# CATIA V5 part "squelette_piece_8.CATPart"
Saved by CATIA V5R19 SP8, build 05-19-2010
Part number: squelette_piece_8
Publications: "Droite.1", "Point.2", "Point.1", "Droite.2", "Droite.3", "Plan.1"
Bounding box of the stored display mesh (mm): x -56 to 58, y 63.5 to 66.858, z -240.184 to 345.816
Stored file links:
  G:\EU_thinkMotion\CFAO_2010\SIL_groupe1\SIL_groupe1\A reprendre\lalpha\lalpha\Alpha.mécanisme\squelette_piece_8.CATPart
  G:\EU_thinkMotion\CFAO_2010\SIL_groupe1\SIL_groupe1\A reprendre\lalpha\lalpha\Alpha.mécanisme\bielle7.CATPart
  G:\EU_thinkMotion\CFAO_2010\SIL_groupe1\SIL_groupe1\A reprendre\lalpha\lalpha\Alpha.mécanisme\squelette_bati.CATPart
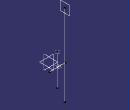
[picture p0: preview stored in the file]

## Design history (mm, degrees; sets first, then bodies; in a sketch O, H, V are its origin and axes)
Body1 (main body)
  Point1: stored without definition
  Point2: stored without definition
  Line1: type PtPt, FirstPoint Point1, SecondPoint Point2, Start 58, End 41
  DatumPoint1
  Line2: type PtPt, FirstPoint Point1, SecondPoint DatumPoint1, Start 131
  Line3: stored without definition
  Plane1: type OffsetPt, RefPlane yz-plane, RefPoint vertex of Line3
